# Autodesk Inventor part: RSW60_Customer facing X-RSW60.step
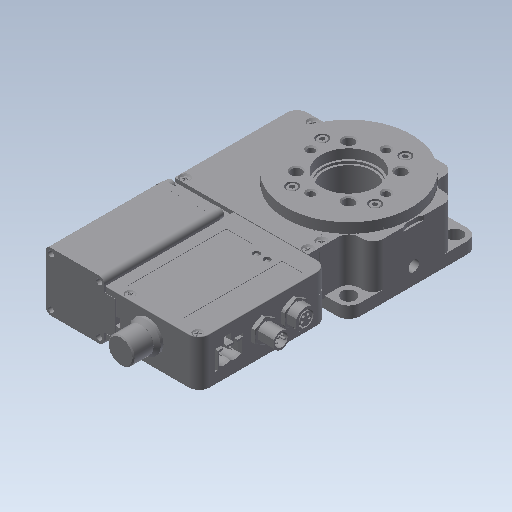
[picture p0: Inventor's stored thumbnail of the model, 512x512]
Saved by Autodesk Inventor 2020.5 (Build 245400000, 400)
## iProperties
RuleStatus: InUse
AfterDocSave0: file://Part Number Cleaner
Created: 2018-04
Material: Generic
Catalog Web Link: https://www.janelia.org/
Vendor: HHMI: JRC - jET
Document SubType Name: Modeling
Designer: goulett
Density: 1 g/cm^3
Appearance: Default
LAB/DEPT: A. LEE (LAB)
DESIGN DEPARTMENT: HHMI: JRC - jET
ALTERED ITEM PART NUMBER: N/A
ALTERED ITEM VENDOR: N/A
ALTERED ITEM DESCRIPTION: N/A
Revision: ANY
Title: RSW60_Customer facing X-RSW60.step
Description: STEP AP203
Sending System: SolidWorks 2015
Preprocessor: SwSTEP 2.0
Title: Standard
Author: goulett
Revision Number: 0
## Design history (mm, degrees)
feature "RSW60 Base-1-solid1"
feature "RSW60 Main Bearing ASMB-1_RSW60 Center Fix-1-solid1"
feature "RSW60 Main Bearing ASMB-1_RSW60 Top-2-solid1"
feature "RSW60 Main Bearing ASMB-1_Screw M2.5 x 10 SC-1-solid1"
feature "RSW60 Main Bearing ASMB-1_Screw M2.5 x 10 SC-2-solid1"
feature "RSW60 Main Bearing ASMB-1_Screw M2.5 x 10 SC-3-solid1"
feature "RSW60 Main Bearing ASMB-1_Screw M2.5 x 10 SC-4-solid1"
feature "Stepper Motor - NEMA11-052mm( C)-1.50A-Single-1-solid1"
feature "RSW60 Housing Lid-1-solid1"
feature "Screw M2.5 x 6 SC-1-solid1"
feature "Screw M2.5 x 6 SC-2-solid1"
feature "Screw M2.5 x 6 SC-3-solid1"
feature "Screw M2.5 x 6 SC-4-solid1"
feature "Screw M2.5 x 4 SC-1-solid1"
feature "Screw M2.5 x 4 SC-2-solid1"
feature "Screw M2.5 x 4 SC-3-solid1"
feature "Screw M2.5 x 4 SC-4-solid1"
feature "Screw, M2x04 McMaster[92010A001]-2-solid1"
feature "Screw, M2x04 McMaster[92010A001]-3-solid1"
feature "Screw, M2x04 McMaster[92010A001]-4-solid1"
feature "Screw, M2x04 McMaster[92010A001]-7-solid1"
feature "Screw, M2x04 McMaster[92010A001]-8-solid1"
feature "Screw, M2x04 McMaster[92010A001]-1-solid1"
feature "X-RSW60 Controller-1_Vega Board Assembly-1_Vega Board-1-soli"
feature "X-RSW60 Controller-1_Vega Board Assembly-1_Nut, M8 Connector"
feature "X-RSW60 Controller-1_Vega Board Assembly-1_Nut, M8 Connector"
feature "X-RSW60 Controller-1_Vega Board Assembly-1_Terminal Block, 5"
feature "X-RSW60 Controller-1_Vega Board Assembly-1_Encoder_Switch-2-"
feature "X-RSW60 Controller-1_Vega Board Assembly-1_Encoder_Switch-2-"
feature "X-RSW60 Controller-1_Vega Board Assembly-1_Connector, M8-1-s"
feature "X-RSW60 Controller-1_Vega Board Assembly-1_Connector, M8-1-s"
feature "X-RSW60 Controller-1_Vega Board Assembly-1_Connector, M8-2-s"
feature "X-RSW60 Controller-1_Vega Board Assembly-1_Connector, M8-2-s"
feature "X-RSW60 Controller-1_Vega Board Assembly-1_Vertical Light Gu"
feature "X-RSW60 Controller-1_Vega Board Assembly-1_Vertical Light Gu"
feature "X-RSW60 Controller-1_Vega Board Assembly-1_Connector, Molex "
feature "X-RSW60 Controller-1_Vega Board Assembly-1_Connector, Molex "
feature "X-RSW60 Controller-1_Vega Board Assembly-1_Connector, Molex "
feature "X-RSW60 Controller-1_Vega Board Assembly-1_Connector, Molex "
feature "X-RSW60 Controller-1_Vega Board Assembly-1_Connector, Molex "
feature "X-RSW60 Controller-1_X-RSW60 Controller Bottom-1-solid1"
feature "X-RSW60 Controller-1_X-RSW60 Controller Top Plastic-1-solid1"
feature "X-RSW60 Controller-1_knob_LA-1-solid1"
feature "X-RSW60 Controller-1_Screw M2 x 16 Flat Head Phillips-1-soli"
feature "X-RSW60 Controller-1_Screw M2 x 16 Flat Head Phillips-2-soli"
body "Solid1"
body "Solid2"
body "Solid3"
body "Solid4"
body "Solid5"
body "Solid6"
body "Solid7"
body "Solid8"
body "Solid9"
body "Solid10"
body "Solid11"
body "Solid12"
body "Solid13"
body "Solid14"
body "Solid15"
body "Solid16"
body "Solid17"
body "Solid18"
body "Solid19"
body "Solid20"
body "Solid21"
body "Solid22"
body "Solid23"
body "Solid24"
body "Solid25"
body "Solid26"
body "Solid27"
body "Solid28"
body "Solid29"
body "Solid30"
body "Solid31"
body "Solid32"
body "Solid33"
body "Solid34"
body "Solid35"
body "Solid36"
body "Solid37"
body "Solid38"
body "Solid39"
body "Solid40"
body "Solid41"
body "Solid42"
body "Solid43"
body "Solid44"
body "Solid45"
